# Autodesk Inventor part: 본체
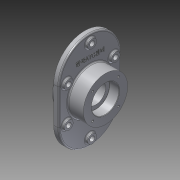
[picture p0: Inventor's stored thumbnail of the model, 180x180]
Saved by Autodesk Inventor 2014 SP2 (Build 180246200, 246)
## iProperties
Created: 2015-02
Part Number: 본체
Material: 알루미늄 6061
Document SubType Name: Modeling
Designer: 201-08
Density: 2.71 g/cm^3
Appearance: 알루미늄 - 평지
Mass: 1623.12 g
Surface Area: 916.453 cm^2
Volume: 598.938 cm^3
Author: 201-08
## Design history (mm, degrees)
sketch "스케치1"
  geometry: L1 (0, 40)-(0, -40); L2 (-70, 40)-(-70, -40); L3 (70, -40)-(70, 40); A1 r 70 centre (0, 40) between (70, 40) and (-70, 40); A2 r 70 centre (0, -40) between (-70, -40) and (70, -40); 3 further points
  constraints: 8 end point, 4 point on circle, 4 tangent, 2 centre point, 2 midpoint, 1 horizontal alignment, 1 parallel, 1 vertical
  dimensions: "d1" = 40 distance of point (0, 0) L1.start; "d3" = 140 distance between parallel lines of L3 L2; "d6" = 70 distance from line of point (0, 0) L3
extrude "돌출1" new body sketch "스케치1" distance "d7" = 12; taper "d8" = 0 deg
sketch "스케치3"
  geometry: C1 r 50 at (0, 0); 1 further point
  constraints: 1 centre point, 1 coincident
  dimensions: "d9" = 50 radius of C1
extrude "돌출2" join sketch "스케치3" distance "d10" = 35; taper "d11" = 0 deg
sketch "스케치4"
  geometry: C1 r 50 at (0, 0); 1 further point
  constraints: 1 centre point, 1 coincident
  dimensions: "d12" = 50 radius of C1
extrude "돌출3" join sketch "스케치4" distance "d13" = 23; taper "d14" = 0 deg
sketch "스케치5"
  geometry: C1 r 31 at (0, 0); 1 further point
  constraints: 1 centre point, 1 coincident
  dimensions: "d15" = 31 radius of C1
extrude "돌출4" cut sketch "스케치5" distance "d16" = 22; taper "d17" = 0 deg
sketch "스케치6"
  geometry: C1 r 31 at (0, 0); 1 further point
  constraints: 1 centre point, 1 coincident
  dimensions: "d18" = 31 radius of C1
extrude "돌출5" cut sketch "스케치6" distance "d19" = 22; taper "d20" = 0 deg
sketch "스케치7"
  geometry: C1 r 22.5 at (0, 0); 1 further point
  constraints: 1 centre point, 1 coincident
  dimensions: "d21" = 22.5 radius of C1
extrude "돌출6" cut sketch "스케치7" stored distance "d22" = 22; taper "d23" = 0 deg
sketch "스케치8"
  geometry: L1 (-40, -70)-(40, -70) reference; L2 (40, 70)-(-40, 70) reference; L3 (-40, -53)-(40, -53); L4 (40, 53)-(-40, 53); C1 r 50 at (0, 0) reference; C2 r 10 at (-93, 0); C3 r 10 at (93, 0); C4 r 10 at (-40, -53); C5 r 10 at (40, -53); C6 r 10 at (40, 53); C7 r 10 at (-40, 53); A1 r 70 centre (40, 0) between (40, -70) and (40, 70) reference; A2 r 70 centre (-40, 0) between (-40, 70) and (-40, -70) reference; A3 r 53 centre (40, 0) between (40, -53) and (40, 53); A4 r 53 centre (-40, 0) between (-40, 53) and (-40, -53); 1 further point
  constraints: 8 centre point, 6 point on circle, 4 coincident, 4 end point, 3 other
  dimensions: "d24" = 17 distance between parallel lines of L1 L3; "d25" = 10 radius of C2; "d26" = 10 radius of C3; "d27" = 10 radius of C4; "d28" = 10 radius of C5; "d29" = 10 radius of C6; "d30" = 10 radius of C7
extrude "돌출7" join sketch "스케치8" distance "d31" = 5; taper "d32" = 0 deg
sketch "스케치9"
  geometry: C1 r 10 at (0, 0) reference; C2 r 10 at (53, -53) reference; C3 r 10 at (133, -53) reference; C4 r 10 at (186, 0) reference; C5 r 10 at (133, 53) reference; C6 r 10 at (53, 53) reference; C7 r 5.5 at (0, 0); C8 r 5.5 at (53, -53); C9 r 5.5 at (133, -53); C10 r 5.5 at (186, 0); C11 r 5.5 at (133, 53); C12 r 5.5 at (53, 53); 1 further point
  constraints: 6 centre point, 6 coincident
  dimensions: "d33" = 5.5 radius of C7; "d34" = 5.5 radius of C8; "d35" = 5.5 radius of C9; "d36" = 5.5 radius of C10; "d37" = 5.5 radius of C11; "d38" = 5.5 radius of C12
extrude "돌출8" cut sketch "스케치9" distance "d39" = 37.25; taper "d40" = 0 deg
sketch "스케치10" dims "d41" = 41
  geometry: L1 (0, 0)-(-33.664, -33.664); L2 (0, 0)-(47.608, 0); L3 (0, 0)-(33.664, -33.664); L4 (0, 0)-(33.664, 33.664); L5 (0, 0)-(-33.664, 33.664); 5 further points
  constraints: 10 end point, 4 point on line, 3 coincident, 1 equal length, 1 horizontal, 18 other
  dimensions: "d42" = 135 deg angle of L1 L2; "d45" = 360 deg dimension on L1.start L1.end (derived)
hole "구멍1" sketch "스케치10" at (-28.991, -28.991), (28.991, -28.991), (28.991, 28.991), (-28.991, 28.991) diameter "d47" = 4.917; stored, may be unused: countersink angle "d51" = 90 deg, drill point angle "d53" = 118 deg; dims "d48" = 10, "d49" = 4, "d50" = 2, "d52" = 13
sketch "스케치11" dims "d54" = 41
  geometry: L1 (0, 0)-(31.336, 31.336); L2 (0, 0)-(44.316, 0); L3 (0, 0)-(-31.336, 31.336); L4 (0, 0)-(-31.336, -31.336); L5 (0, 0)-(31.336, -31.336); 5 further points
  constraints: 10 end point, 4 point on line, 3 coincident, 1 equal length, 1 horizontal, 18 other
  dimensions: "d55" = 45 deg angle of L2 L1; "d58" = 360 deg dimension on L1.start L1.end (derived)
hole "구멍2" sketch "스케치11" at (28.991, 28.991), (-28.991, 28.991), (-28.991, -28.991), (28.991, -28.991) diameter "d60" = 4.917; stored, may be unused: countersink angle "d64" = 90 deg, drill point angle "d66" = 118 deg; dims "d61" = 10, "d62" = 4, "d63" = 2, "d65" = 13
node "작업 평면1"
sketch "스케치12"
  geometry: 2 further points
  constraints: 1 vertical alignment, 1 other
  dimensions: "d68" = 65 distance of point (0, 0) point (0, 65)
feature "엠보싱1" sketch "스케치12" dims "d1" = 40, "d3" = 140, "d6" = 70, "d15" = 31, "d69" = 1, "d70" = 0
fillet "모깎기1" dims "d71" = 0.3
fillet "모깎기2" dims "d72" = 3
chamfer "모따기1" distance "d73" = 1; stored, may be unused: second distance "d74" = 2, angle "d75" = 45 deg
node "솔리드1"
node "투영된 루프1"
node "투영된 루프2"
node "투영된 루프3"
node "투영된 루프4"
node "투영된 루프5"
node "투영된 루프6"
node "투영된 루프7"
other parameters: "d67" = 105.5
